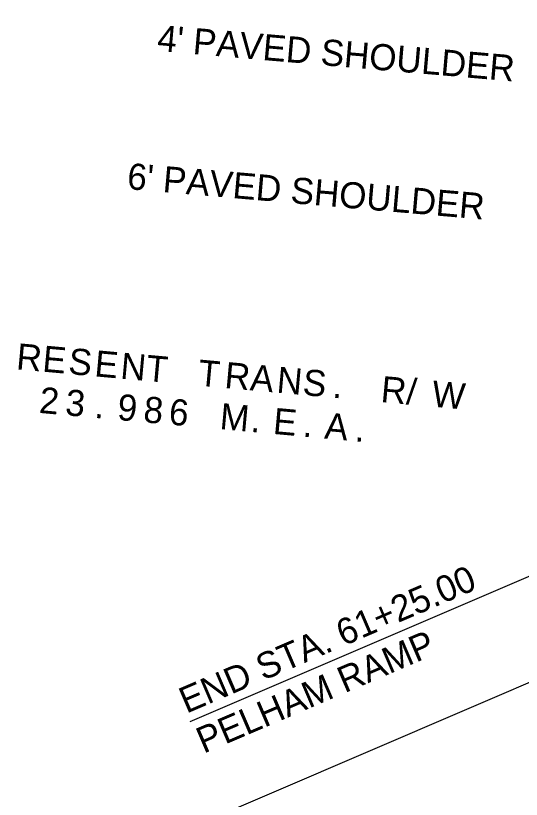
# Model space of a CAD drawing. Extents: x 1621035 to 1623496, y 1102384 to 1103996.
# Drawn here: x 1621819.8 to 1621935.9, y 1102564.1 to 1102744 of the extents above; entities that cross this region are included whole.
import ezdxf

# ---------------------------------------------------------------- set-up
doc = ezdxf.new("R2010")
doc.units = 0
for name, color, linetype in [('RD_EX_DV_TX_Prop', 7, 'Continuous'), ('RD_EX_RW', 7, 'Continuous'), ('RD_PD_Final_TX', 7, 'Continuous')]:
    doc.layers.add(name, color=color, linetype=linetype)

msp = doc.modelspace()

# ---------------------------------------------------------------- linework, layer by layer
at = {"layer": 'RD_EX_RW'}
msp.add_line((1621950.95, 1102621.01), (1621859.78, 1102581.89), dxfattribs=at)
at = {"layer": 'RD_PD_Final_TX'}
msp.add_lwpolyline([(1621300.09, 1102746.85), (1621324.02, 1102752.88), (1621344.3, 1102622.52), (1621455.74, 1102384.16), (1622813.61, 1102966.94), (1622454.69, 1103803.24), (1622329.06, 1103749.66), (1622314.99, 1103780.87), (1621083.19, 1103252.2)], close=True, dxfattribs=at)
msp.add_lwpolyline([(1621300.09, 1102746.85), (1621324.02, 1102752.88), (1621344.3, 1102622.52), (1621455.74, 1102384.16), (1622813.61, 1102966.94), (1622454.69, 1103803.24), (1622329.06, 1103749.66), (1622314.99, 1103780.87), (1621083.19, 1103252.2)], close=True, dxfattribs=at)

# ---------------------------------------------------------------- texts
at = {"layer": 'RD_EX_DV_TX_Prop'}
for s, p in [('R', (1621819.79, 1102662.83)), ('E', (1621825.79, 1102662.3)), ('S', (1621831.74, 1102661.76)), ('E', (1621837.74, 1102661.22)), ('N', (1621843.69, 1102660.69)), ('T', (1621849.55, 1102660.16)), ('T', (1621861.5, 1102659.08)), ('R', (1621867.59, 1102658.54)), ('A', (1621873.45, 1102658.01)), ('N', (1621879.55, 1102657.46)), ('S', (1621885.52, 1102656.93)), ('R', (1621903.45, 1102655.31)), ('/', (1621909.31, 1102654.79)), ('W', (1621915.14, 1102654.26)), ('2', (1621825.05, 1102652.82)), ('3', (1621831.03, 1102652.29)), ('9', (1621842.98, 1102651.21)), ('8', (1621848.96, 1102650.67)), ('.', (1621892.39, 1102656.31)), ('6', (1621854.79, 1102650.15)), ('M', (1621866.49, 1102649.1)), ('E', (1621878.72, 1102648)), ('A', (1621890.53, 1102646.94)), ('.', (1621837.76, 1102651.68)), ('.', (1621873.61, 1102648.46)), ('.', (1621885.57, 1102647.38)), ('.', (1621897.52, 1102646.31))]:
    msp.add_text(s, height=6, rotation=354.8631, dxfattribs=at).set_placement(p)
at = {"layer": 'RD_EX_RW'}
for s, rotation, p in [("4' PAVED SHOULDER", 355.0927, (1621852.13, 1102735.92)), ("6' PAVED SHOULDER", 355.0927, (1621845.23, 1102704.22)), ('END STA. 61+25.00', 23.2267, (1621858.99, 1102583.72)), ('PELHAM RAMP', 23.2267, (1621862.94, 1102574.53))]:
    msp.add_text(s, height=6, rotation=rotation, dxfattribs=at).set_placement(p)

doc.saveas('drawing.dxf')
